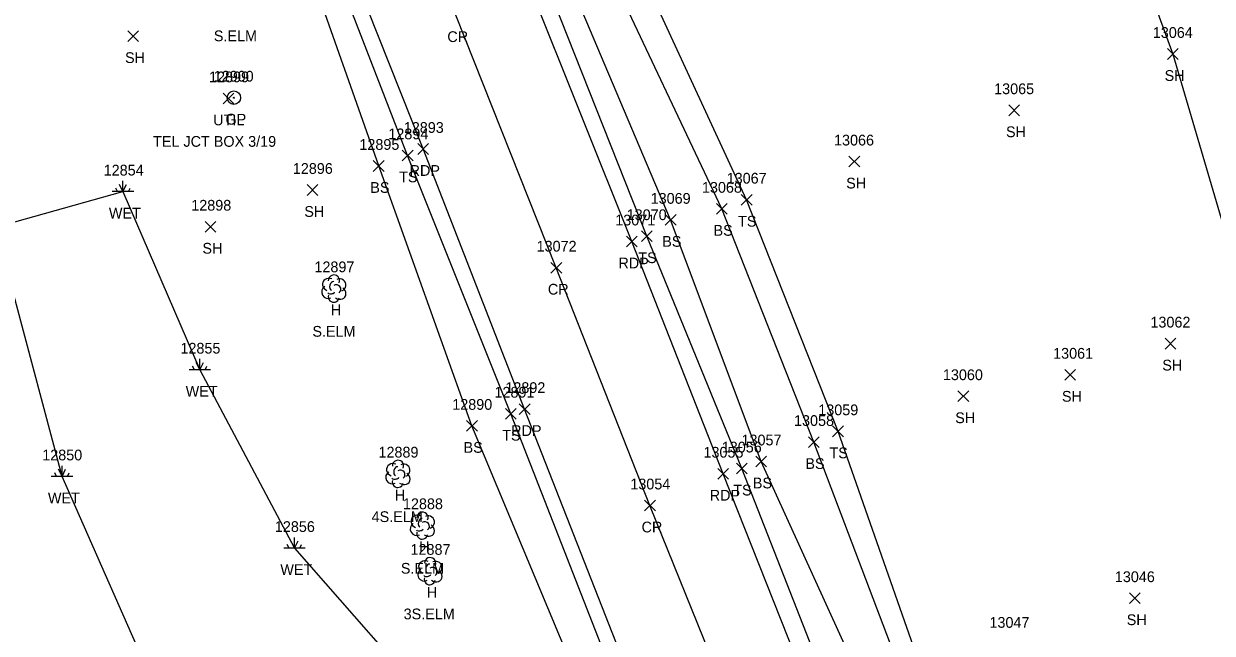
# Model space of a CAD drawing. Extents: x 1439173 to 1457902, y 641926 to 659889.
# Drawn here: x 1447459.9 to 1447680.9, y 650118.5 to 650231.9 of the extents above; entities that cross this region are included whole.
import ezdxf

# ---------------------------------------------------------------- set-up
doc = ezdxf.new("R2010")
doc.units = 0
for name, color, linetype in [('L_A', 7, 'Continuous'), ('L_C', 7, 'Continuous'), ('L_I', 7, 'Continuous'), ('L_TIC', 7, 'Continuous'), ('LELB', 7, 'Continuous'), ('LSOGP', 7, 'Continuous'), ('LTD', 7, 'Continuous'), ('LWET', 7, 'Continuous'), ('P_A', 7, 'Continuous'), ('P_I', 7, 'Continuous'), ('P_TIC', 7, 'Continuous'), ('PET', 7, 'Continuous'), ('PRC', 7, 'Continuous'), ('R_A', 7, 'Continuous'), ('R_I', 7, 'Continuous'), ('RGP', 7, 'Continuous'), ('U_A', 7, 'Continuous'), ('U_C', 7, 'Continuous'), ('U_I', 7, 'Continuous'), ('UDEFAULT', 7, 'Continuous')]:
    doc.layers.add(name, color=color, linetype=linetype)

msp = doc.modelspace()

# ---------------------------------------------------------------- linework, layer by layer
at = {"layer": 'L_TIC'}
for points in [[(1447479.21, 650228.59), (1447481.21, 650230.59)], [(1447481.21, 650228.59), (1447479.21, 650230.59)], [(1447672.57, 650225.26), (1447674.57, 650227.26)], [(1447674.57, 650225.26), (1447672.57, 650227.26)], [(1447643.07, 650214.79), (1447645.07, 650216.79)], [(1447645.07, 650214.79), (1447643.07, 650216.79)], [(1447530.27, 650206.4), (1447532.27, 650208.4)], [(1447532.27, 650206.4), (1447530.27, 650208.4)], [(1447524.88, 650204.43), (1447526.88, 650206.43)], [(1447526.88, 650204.43), (1447524.88, 650206.43)], [(1447613.35, 650205.24), (1447615.35, 650207.24)], [(1447615.35, 650205.24), (1447613.35, 650207.24)], [(1447512.56, 650199.96), (1447514.56, 650201.96)], [(1447514.56, 650199.96), (1447512.56, 650201.96)], [(1447593.32, 650198.15), (1447595.32, 650200.15)], [(1447595.32, 650198.15), (1447593.32, 650200.15)], [(1447588.72, 650196.45), (1447590.72, 650198.45)], [(1447590.72, 650196.45), (1447588.72, 650198.45)], [(1447493.61, 650193.12), (1447495.61, 650195.12)], [(1447495.61, 650193.12), (1447493.61, 650195.12)], [(1447579.18, 650194.4), (1447581.18, 650196.4)], [(1447581.18, 650194.4), (1447579.18, 650196.4)], [(1447574.75, 650191.36), (1447576.75, 650193.36)], [(1447576.75, 650191.36), (1447574.75, 650193.36)], [(1447672.14, 650171.37), (1447674.14, 650173.37)], [(1447674.14, 650171.37), (1447672.14, 650173.37)], [(1447653.47, 650165.57), (1447655.47, 650167.57)], [(1447655.47, 650165.57), (1447653.47, 650167.57)], [(1447633.62, 650161.58), (1447635.62, 650163.58)], [(1447635.62, 650161.58), (1447633.62, 650163.58)], [(1447549.44, 650158.33), (1447551.44, 650160.33)], [(1447551.44, 650158.33), (1447549.44, 650160.33)], [(1447542.23, 650156.06), (1447544.23, 650158.06)], [(1447544.23, 650156.06), (1447542.23, 650158.06)], [(1447610.31, 650155.05), (1447612.31, 650157.05)], [(1447612.31, 650155.05), (1447610.31, 650157.05)], [(1447605.8, 650153.06), (1447607.8, 650155.06)], [(1447607.8, 650153.06), (1447605.8, 650155.06)], [(1447592.41, 650148.12), (1447594.41, 650150.12)], [(1447594.41, 650148.12), (1447592.41, 650150.12)], [(1447596.03, 650149.44), (1447598.03, 650151.44)], [(1447598.03, 650149.44), (1447596.03, 650151.44)], [(1447665.52, 650124), (1447667.52, 650126)], [(1447667.52, 650124), (1447665.52, 650126)]]:
    msp.add_lwpolyline(points, dxfattribs=at)
at = {"layer": 'LELB'}
for points in [[(1447571.48, 650089.35), (1447543.23, 650157.06), (1447525.88, 650205.43), (1447512.98, 650242.23), (1447494, 650287.33), (1447479.44, 650328.05), (1447463.02, 650363.87), (1447448.53, 650409.18), (1447433.9, 650446.13), (1447414.28, 650494.66), (1447400.06, 650532.32), (1447379.5, 650582.12), (1447364.35, 650622.06), (1447346.64, 650667.82), (1447331.93, 650703.62), (1447316.98, 650738.43), (1447312.39, 650753.19), (1447291.07, 650804.17), (1447278.89, 650834.3), (1447266.96, 650868.41), (1447255.25, 650904.29)], [(1447647.66, 650051.11), (1447635.8, 650076.23), (1447623.63, 650109.75), (1447606.8, 650154.06), (1447589.72, 650197.45), (1447568.07, 650243.28), (1447552.5, 650284.76), (1447533.68, 650328.89), (1447516.95, 650382.09), (1447502.38, 650426.41), (1447489.88, 650466.38), (1447470.65, 650514.37), (1447457.04, 650551.19), (1447438.81, 650599.31), (1447426.73, 650643.05), (1447409.28, 650692.38), (1447398, 650730.45), (1447389.2, 650748.42), (1447378.46, 650777.36), (1447369.33, 650793.38), (1447353.32, 650811.59), (1447344.39, 650816.56)], [(1447647.66, 650051.11), (1447639.02, 650077.81), (1447627.07, 650111.08), (1447611.31, 650156.05), (1447594.32, 650199.15), (1447573.11, 650245.07), (1447556.36, 650286.01), (1447537.25, 650330.04), (1447520.36, 650383.07), (1447505.02, 650426.74), (1447494.09, 650467.63), (1447475.67, 650515.79), (1447464.85, 650554.26), (1447445.85, 650603.05), (1447431.83, 650644.08), (1447421.52, 650673.15)], [(1447668.69, 649987.09), (1447664.08, 649999.32), (1447646.02, 650028.75), (1447630.2, 650073.24), (1447616.75, 650107.14), (1447597.03, 650150.44), (1447580.18, 650195.4), (1447560.83, 650241.21), (1447545.29, 650281.91), (1447527.82, 650326.29), (1447510.36, 650380.27)], [(1447774.29, 649691.46), (1447755.02, 649740.49), (1447741.76, 649773.81), (1447726.53, 649815.31), (1447711.79, 649851.58), (1447694.8, 649894.93), (1447679.35, 649935.48), (1447671.24, 649953.99), (1447664.82, 649972.77), (1447658.14, 649990.48), (1447642.81, 650028.26), (1447624.72, 650071.67), (1447610.83, 650104.7), (1447593.41, 650149.12), (1447575.75, 650192.36), (1447557, 650239.72), (1447541.41, 650280.13), (1447523.46, 650325.06), (1447503.16, 650377.6)], [(1447557.08, 650018.09), (1447576.08, 650025.78), (1447590.3, 650036.08), (1447592.03, 650051.14), (1447577.18, 650090.92), (1447550.44, 650159.33), (1447531.27, 650207.4), (1447516.88, 650244.59), (1447498.86, 650290.07), (1447483.09, 650328.7), (1447468.16, 650366.57)]]:
    msp.add_lwpolyline(points, dxfattribs=at)
at = {"layer": 'LSOGP'}
msp.add_lwpolyline([(1447619.03, 650360.07), (1447637.42, 650315.88), (1447658.67, 650267.12), (1447673.57, 650226.26), (1447688.13, 650176.69), (1447711.15, 650147.55), (1447725.49, 650099.49), (1447742.44, 650053.11), (1447746.12, 650031.62), (1447770.15, 650000.07), (1447776.52, 649966.69), (1447797.12, 649942.22), (1447810.31, 649916.5), (1447819.33, 649880.31), (1447829.59, 649850.37), (1447834.46, 649819.36), (1447847.14, 649760.71), (1447857.32, 649718.69)], dxfattribs=at)
at = {"layer": 'LTD'}
for p, q in [((1447517.52, 650182.66), (1447517.52, 650182.66)), ((1447517.52, 650182.66), (1447517.52, 650182.66)), ((1447529.44, 650148.18), (1447529.44, 650148.18)), ((1447529.44, 650148.18), (1447529.44, 650148.18)), ((1447533.98, 650138.57), (1447533.98, 650138.57)), ((1447533.98, 650138.57), (1447533.98, 650138.57)), ((1447535.39, 650130.08), (1447535.39, 650130.08)), ((1447535.39, 650130.08), (1447535.39, 650130.08))]:
    msp.add_line(p, q, dxfattribs=at)
for centre in [(1447517.56, 650184.1), (1447529.48, 650149.62), (1447534.03, 650140), (1447535.44, 650131.52)]:
    msp.add_arc(centre, 1.05, 335.5272, 180.9563, dxfattribs=at)
for centre, major_axis, ratio, start_param, end_param in [((1447516.72, 650183.33), (1.21, -0.51), 0.895232, 1.570796, 4.712389), ((1447517.31, 650183.12), (-0.208, -0.792), 0.645439, 3.141593, 6.283185), ((1447518.02, 650182.5), (-0.5, 0.667), 0.989748, 3.141593, 6.283185), ((1447518.56, 650183.25), (-1.14, -0.48), 0.949671, 1.570796, 4.712389), ((1447516.43, 650181.95), (0.58, -1.04), 0.959034, 3.141593, 6.283185), ((1447517.52, 650181.16), (0.26, 1.06), 0.942809, 1.570796, 4.712389), ((1447517.06, 650181.91), (-0.625, -0.083), 0.423636, 0, 3.141593), ((1447518.52, 650181.83), (-1.09, 0.79), 0.841452, 1.570796, 4.712389), ((1447528.64, 650148.85), (1.21, -0.51), 0.895232, 1.570796, 4.712389), ((1447530.48, 650148.77), (-1.14, -0.48), 0.949671, 1.570796, 4.712389), ((1447528.35, 650147.47), (0.58, -1.04), 0.959034, 3.141593, 6.283185), ((1447529.23, 650148.64), (-0.208, -0.792), 0.645439, 3.141593, 6.283185), ((1447529.94, 650148.02), (-0.5, 0.667), 0.989748, 3.141593, 6.283185), ((1447530.44, 650147.35), (-1.09, 0.79), 0.841452, 1.570796, 4.712389), ((1447529.44, 650146.68), (0.26, 1.06), 0.942809, 1.570796, 4.712389), ((1447528.98, 650147.43), (-0.625, -0.083), 0.423636, 0, 3.141593), ((1447533.19, 650139.24), (1.21, -0.51), 0.895232, 1.570796, 4.712389), ((1447533.77, 650139.03), (-0.208, -0.792), 0.645439, 3.141593, 6.283185), ((1447534.48, 650138.4), (-0.5, 0.667), 0.989748, 3.141593, 6.283185), ((1447535.02, 650139.15), (-1.14, -0.48), 0.949671, 1.570796, 4.712389), ((1447532.9, 650137.86), (0.58, -1.04), 0.959034, 3.141593, 6.283185), ((1447533.98, 650137.07), (0.26, 1.06), 0.942809, 1.570796, 4.712389), ((1447533.52, 650137.82), (-0.625, -0.083), 0.423636, 0, 3.141593), ((1447534.98, 650137.74), (-1.09, 0.79), 0.841452, 1.570796, 4.712389), ((1447534.31, 650129.38), (0.58, -1.04), 0.959034, 3.141593, 6.283185), ((1447534.6, 650130.75), (1.21, -0.51), 0.895232, 1.570796, 4.712389), ((1447535.18, 650130.54), (-0.208, -0.792), 0.645439, 3.141593, 6.283185), ((1447535.89, 650129.92), (-0.5, 0.667), 0.989748, 3.141593, 6.283185), ((1447536.43, 650130.67), (-1.14, -0.48), 0.949671, 1.570796, 4.712389), ((1447535.39, 650128.58), (0.26, 1.06), 0.942809, 1.570796, 4.712389), ((1447534.93, 650129.33), (-0.625, -0.083), 0.423636, 0, 3.141593), ((1447536.39, 650129.25), (-1.09, 0.79), 0.841452, 1.570796, 4.712389)]:
    msp.add_ellipse(centre, major_axis=major_axis, ratio=ratio, start_param=start_param, end_param=end_param, dxfattribs=at)
at = {"layer": 'LWET'}
for p, q in [((1447477.32, 650200.65), (1447476.99, 650201.31)), ((1447478.32, 650200.65), (1447477.66, 650201.98)), ((1447478.32, 650200.65), (1447478.32, 650202.65)), ((1447478.32, 650200.65), (1447478.99, 650201.98)), ((1447479.32, 650200.65), (1447479.66, 650201.31)), ((1447480.32, 650200.65), (1447476.32, 650200.65)), ((1447491.6, 650167.52), (1447491.27, 650168.18)), ((1447492.6, 650167.52), (1447491.93, 650168.85)), ((1447492.6, 650167.52), (1447492.6, 650169.52)), ((1447492.6, 650167.52), (1447493.27, 650168.85)), ((1447493.6, 650167.52), (1447493.93, 650168.18)), ((1447494.6, 650167.52), (1447490.6, 650167.52)), ((1447465.98, 650147.65), (1447465.65, 650148.32)), ((1447466.98, 650147.65), (1447466.31, 650148.99)), ((1447466.98, 650147.65), (1447466.98, 650149.65)), ((1447466.98, 650147.65), (1447467.65, 650148.99)), ((1447467.98, 650147.65), (1447468.31, 650148.32)), ((1447468.98, 650147.65), (1447464.98, 650147.65)), ((1447509.21, 650134.33), (1447508.88, 650134.99)), ((1447510.21, 650134.33), (1447509.55, 650135.66)), ((1447510.21, 650134.33), (1447510.21, 650136.33)), ((1447510.21, 650134.33), (1447510.88, 650135.66)), ((1447511.21, 650134.33), (1447511.55, 650134.99)), ((1447512.21, 650134.33), (1447508.21, 650134.33))]:
    msp.add_line(p, q, dxfattribs=at)
msp.add_lwpolyline([(1447516.64, 650036.78), (1447503.11, 650057.19), (1447493.49, 650080.26), (1447485.66, 650105.31), (1447466.98, 650147.65), (1447454.61, 650194.03), (1447478.32, 650200.65), (1447492.6, 650167.52), (1447510.21, 650134.33), (1447538.19, 650102.42), (1447553.74, 650083.39), (1447557.32, 650093.03)], dxfattribs=at)
at = {"layer": 'P_TIC'}
for points in [[(1447533.14, 650207.59), (1447535.14, 650209.59)], [(1447535.14, 650207.59), (1447533.14, 650209.59)], [(1447571.98, 650190.37), (1447573.98, 650192.37)], [(1447573.98, 650190.37), (1447571.98, 650192.37)], [(1447557.92, 650185.5), (1447559.92, 650187.5)], [(1447559.92, 650185.5), (1447557.92, 650187.5)], [(1447552.03, 650159.19), (1447554.03, 650161.19)], [(1447554.03, 650159.19), (1447552.03, 650161.19)], [(1447588.96, 650147.16), (1447590.96, 650149.16)], [(1447590.96, 650147.16), (1447588.96, 650149.16)], [(1447575.34, 650141.25), (1447577.34, 650143.25)], [(1447577.34, 650141.25), (1447575.34, 650143.25)]]:
    msp.add_lwpolyline(points, dxfattribs=at)
at = {"layer": 'PET'}
for points in [[(1447770.26, 649690.21), (1447751.9, 649738.85), (1447739.23, 649772.88), (1447722.51, 649814.14), (1447708.42, 649850.04), (1447690.94, 649894.41), (1447668.44, 649951.98), (1447651.8, 649993.39), (1447639.52, 650024.92), (1447621.07, 650070.34), (1447607.4, 650104.2), (1447589.96, 650148.16), (1447572.98, 650191.37), (1447554, 650238.81), (1447538.2, 650279.02), (1447520.31, 650323.9), (1447499.97, 650376.7)], [(1447727.24, 649719.06), (1447711.09, 649760.24), (1447693.62, 649804.98), (1447680.5, 649838.27), (1447663.74, 649880.79), (1447652.33, 649909.76), (1447638.93, 649943.34), (1447628.9, 649967.78), (1447622.17, 649981.56), (1447611.58, 650013.54), (1447596.45, 650049.26), (1447579.87, 650091.8), (1447553.03, 650160.19), (1447534.14, 650208.59), (1447519.57, 650245.32), (1447501.85, 650290.55), (1447485.96, 650331.56), (1447471.86, 650366.58)]]:
    msp.add_lwpolyline(points, dxfattribs=at)
at = {"layer": 'PRC'}
msp.add_lwpolyline([(1447756.88, 649685.17), (1447724.87, 649768.37), (1447708.6, 649809.19), (1447694.68, 649845.27), (1447676.47, 649890.48), (1447654.25, 649946.92), (1447638.2, 649987.7), (1447625.62, 650020.15), (1447607.06, 650065.42), (1447594.17, 650098.1), (1447576.34, 650142.25), (1447558.92, 650186.5), (1447540.22, 650233.49), (1447524.32, 650273.63), (1447506.57, 650318.67), (1447486.08, 650370.95)], dxfattribs=at)
at = {"layer": 'RGP'}
msp.add_line((1447498.95, 650218.13), (1447498.95, 650218.13), dxfattribs=at)
for radius in [1.25, 0.0833]:
    msp.add_circle((1447498.95, 650218.13), radius, dxfattribs=at)
at = {"layer": 'UDEFAULT'}
for points in [[(1447496.93, 650217), (1447498.93, 650219)], [(1447498.93, 650217), (1447496.93, 650219)]]:
    msp.add_lwpolyline(points, dxfattribs=at)

# ---------------------------------------------------------------- texts
at = {"layer": 'L_A'}
for s, p in [('SH', (1447478.7, 650224.59)), ('SH', (1447672.06, 650221.26)), ('SH', (1447642.56, 650210.79)), ('TS', (1447529.68, 650202.4)), ('SH', (1447612.83, 650201.24)), ('BS', (1447524.32, 650200.43)), ('WET', (1447475.7, 650195.65)), ('SH', (1447512.05, 650195.96)), ('BS', (1447588.16, 650192.45)), ('TS', (1447592.73, 650194.15)), ('BS', (1447578.62, 650190.4)), ('SH', (1447493.1, 650189.12)), ('TS', (1447574.16, 650187.36)), ('H', (1447516.95, 650177.66)), ('SH', (1447671.63, 650167.37)), ('WET', (1447489.98, 650162.52)), ('SH', (1447652.96, 650161.57)), ('SH', (1447633.11, 650157.58)), ('TS', (1447548.85, 650154.33)), ('BS', (1447541.67, 650152.06)), ('TS', (1447609.72, 650151.05)), ('BS', (1447605.24, 650149.06)), ('TS', (1447591.82, 650144.12)), ('BS', (1447595.47, 650145.44)), ('WET', (1447464.36, 650142.65)), ('H', (1447528.87, 650143.18)), ('H', (1447533.41, 650133.57)), ('WET', (1447507.59, 650129.33)), ('H', (1447534.82, 650125.08)), ('SH', (1447665.01, 650120))]:
    msp.add_text(s, height=2, dxfattribs=at).set_placement(p)
at = {"layer": 'L_C'}
for s, p in [('S.ELM', (1447495.22, 650228.64)), ('S.ELM', (1447513.55, 650173.66)), ('4S.ELM', (1447524.57, 650139.18)), ('S.ELM', (1447530.01, 650129.57)), ('3S.ELM', (1447530.52, 650121.08))]:
    msp.add_text(s, height=2, dxfattribs=at).set_placement(p)
at = {"layer": 'L_I'}
for s, p in [('13064', (1447669.86, 650229.26)), ('13065', (1447640.35, 650218.79)), ('12894', (1447527.68, 650210.4)), ('12895', (1447522.29, 650208.43)), ('13066', (1447610.57, 650209.24)), ('12854', (1447474.73, 650203.65)), ('12896', (1447509.91, 650203.96)), ('13067', (1447590.6, 650202.15)), ('13068', (1447586, 650200.45)), ('12898', (1447491.02, 650197.12)), ('13069', (1447576.46, 650198.4)), ('13070', (1447572, 650195.36)), ('12897', (1447513.93, 650185.66)), ('13062', (1447669.42, 650175.37)), ('12855', (1447489.01, 650170.52)), ('13061', (1447651.32, 650169.57)), ('13060', (1447630.82, 650165.58)), ('12891', (1447547.42, 650162.33)), ('12890', (1447539.56, 650160.06)), ('13058', (1447603.13, 650157.06)), ('13059', (1447607.64, 650159.05)), ('13057', (1447593.36, 650153.44)), ('12850', (1447463.3, 650150.65)), ('12889', (1447525.84, 650151.18)), ('13056', (1447589.69, 650152.12)), ('12888', (1447530.39, 650141.57)), ('12856', (1447506.57, 650137.33)), ('12887', (1447531.8, 650133.08)), ('13046', (1447662.8, 650128)), ('13047', (1447639.48, 650119.5))]:
    msp.add_text(s, height=2, dxfattribs=at).set_placement(p)
at = {"layer": 'P_A'}
for s, p in [('CR', (1447538.65, 650228.49)), ('RDP', (1447531.63, 650203.59)), ('RDP', (1447570.47, 650186.37)), ('CR', (1447557.35, 650181.5)), ('RDP', (1447550.52, 650155.19)), ('RDP', (1447587.45, 650143.16)), ('CR', (1447574.78, 650137.25))]:
    msp.add_text(s, height=2, dxfattribs=at).set_placement(p)
at = {"layer": 'P_I'}
for s, p in [('12893', (1447530.55, 650211.59)), ('13071', (1447569.88, 650194.37)), ('13072', (1447555.25, 650189.5)), ('12892', (1447549.44, 650163.19)), ('13055', (1447586.29, 650151.16)), ('13054', (1447572.68, 650145.25))]:
    msp.add_text(s, height=2, dxfattribs=at).set_placement(p)
at = {"layer": 'R_A'}
msp.add_text('GP', height=2, dxfattribs=at).set_placement((1447497.38, 650213.13))
at = {"layer": 'R_I'}
msp.add_text('12900', height=2, dxfattribs=at).set_placement((1447495.19, 650221.13))
at = {"layer": 'U_A'}
msp.add_text('UTIL', height=2, dxfattribs=at).set_placement((1447495.1, 650213))
at = {"layer": 'U_C'}
msp.add_text('TEL JCT BOX 3/19', height=2, dxfattribs=at).set_placement((1447483.92, 650209))
at = {"layer": 'U_I'}
msp.add_text('12899', height=2, dxfattribs=at).set_placement((1447494.33, 650221))

doc.saveas('drawing.dxf')
